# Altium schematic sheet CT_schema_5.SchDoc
size 293 x 258 mm
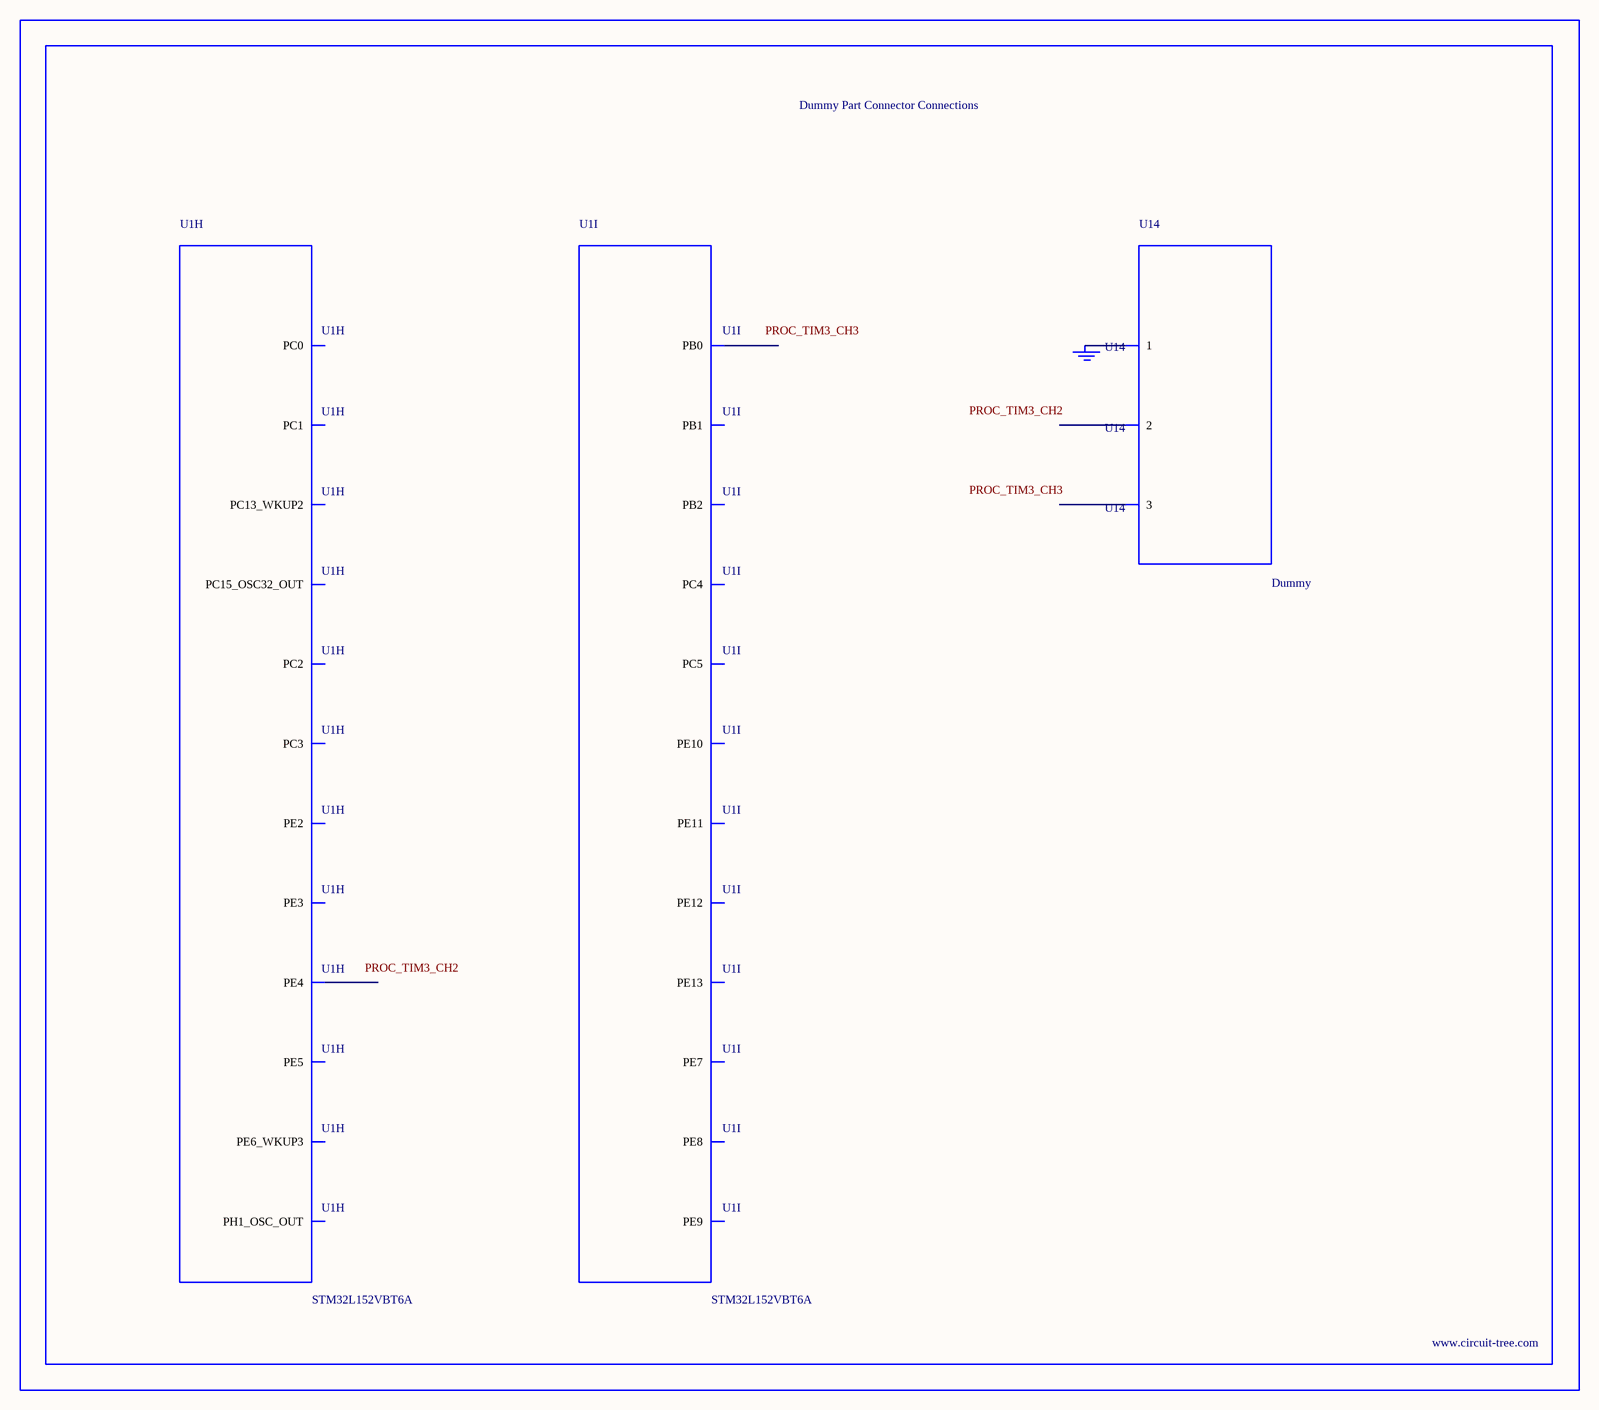
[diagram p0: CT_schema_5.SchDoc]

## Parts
BORDER4  (no value)
GND_INSTANCE_4_0  (no value)
U1  STM32L152VBT6A  [LQFP100]  (parts H,I of 9)
U14  Dummy  [DUMMY_PACKAGE_116]

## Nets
NetGND_INSTANCE_4_0_0: GND_INSTANCE_4_0.0(GND) U14.1

Not connected (* = marked no-connect by the designer): U1 1(PE2) 2(PE3) 3(PE4) 4(PE5) 5(PE6_WKUP3) 7(PC13_WKUP2) 9(PC15_OSC32_OUT) 13(PH1_OSC_OUT) 15(PC0) 16(PC1) 17(PC2) 18(PC3) 33(PC4) 34(PC5) 35(PB0) 36(PB1) 37(PB2) 38(PE7) 39(PE8) 40(PE9) 41(PE10) 42(PE11) 43(PE12) 44(PE13); U14 2 3

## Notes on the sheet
- Labels drawn without touching a wire or pin: PROC_TIM3_CH2, PROC_TIM3_CH3

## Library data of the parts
BORDER4 = BORDER_PAGE4
GND_INSTANCE_4_0 = GND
